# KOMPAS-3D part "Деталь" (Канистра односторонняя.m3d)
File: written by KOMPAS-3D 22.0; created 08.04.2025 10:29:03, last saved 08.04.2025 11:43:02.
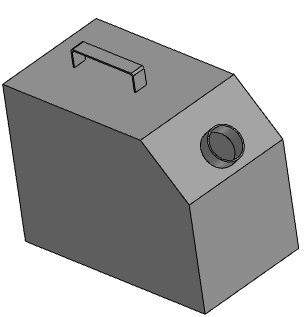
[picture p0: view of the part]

Document properties: Автор: Admin; Полное имя файла: D:\28.11.2016\Абилимпикс\2025\Канистра односторонняя.m3d

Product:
- Part/product: Деталь
    Масса: 4.798699

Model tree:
1. Эскиз:2
2. Элемент выдавливания:2
     Расстояние 1 = 2
3. Элемент выдавливания:3  (with: Элемент выдавливания:2)
     Толщина стенки 2 = 2; Расстояние 1 = 166
4. Эскиз:3  (with: Элемент выдавливания:3)
5. Элемент выдавливания:4
     Расстояние 1 = 2
6. Эскиз:4  (with: Элемент выдавливания:2)
7. Элемент выдавливания:5
     Расстояние 1 = 25
8. Эскиз:5  (with: Элемент выдавливания:5)
9. Элемент выдавливания:6
     Расстояние 1 = 2
10. Скругление:1  (with: Элемент выдавливания:6)
     Радиус = 3
11. Эскиз:6  (with: Элемент выдавливания:2)
12. Элемент выдавливания:7  (with: Элемент выдавливания:2)
     Расстояние 1 = 20
13. Эскиз:7  (with: Элемент выдавливания:7)
14. Элемент выдавливания:8
     Расстояние 2 = 50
